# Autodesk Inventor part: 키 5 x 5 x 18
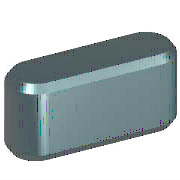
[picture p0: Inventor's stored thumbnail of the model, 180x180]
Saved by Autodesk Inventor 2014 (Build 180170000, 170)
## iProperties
IsCustomPart: 1
Created: 2012-02
Part Number: 키 5 x 5 x 18
Material: 강철, 연강
Description: 키 및 해당 키홈
Document SubType Name: Modeling
Standard: KS B 1311
Designer: mduedu
Standards Organization: KS
Language: ko-KR
Size Designation: 5 x 5 x 18
Categories: <MemberInstance><Categories><Category DisplayName="샤프트 부품" InternalName="7f7aeb1f-a693-4053-b835-cee3144e0d98" Mnemonic="SHFT"><Category DisplayName="키" Interna
Density: 7.86 g/cm^3
Appearance: 금색
Mass: 3.27476 g
Surface Area: 3.57848 cm^2
Volume: 0.416636 cm^3
Author: mduedu
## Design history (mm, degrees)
workplane "Work Plane1"
workplane "Work Plane2"
sketch "스케치1"
  geometry: L1 (2.5, 2.5)-(15.5, 2.5); L2 (15.5, -2.5)-(2.5, -2.5); L3 (0, 9.4)-(0, -7.4) reference; L4 (-5, 0)-(30, 0) reference; L5 (18, 0)-(18, 7); A1 r 2.5 centre (2.5, 0) between (2.5, 2.5) and (2.5, -2.5); A2 r 2.5 centre (15.5, 0) between (15.5, -2.5) and (15.5, 2.5)
  constraints: 6 end point, 5 point on circle, 4 tangent, 3 point on line, 2 centre point, 1 horizontal, 1 parallel, 1 perpendicular
  dimensions: "d0" = 2.5 radius of A1 (= 0.5 x PB); "d13" = 2.5 radius of A2 (= 0.5 x PB); "d14" = 18 distance between parallel lines of L5 L3 (= NLG)
extrude "본체1" new body sketch "스케치1" taper "d3" = 0 deg; stored distance "d4" = 10
workplane "Work Plane3"
body "Solid1"
chamfer "모따기1" distance "d8" = 0.4 (= PHH); stored, may be unused: second distance "d9" = 0.4 (= PHH), angle "d15" = 45 deg
other parameters: "d1" = -3 (= -PNT), "d2" = 2 (= PH - PNT), "NLG" = 18 [user parameter; used in 3 equation terms], "PB" = 5 [user parameter; used in 2 equation terms], "PNT" = 3 [user parameter; used in 2 equation terms], "PH" = 5 [user parameter; used in 1 equation term], "PHH" = 0.4 [user parameter; used in 2 equation terms], "d10" = 0, "d16" = 0, "d17" = 0, "d18" = 0, "WDMIN" = 12 [user parameter], "PLB2" = 18 (= NLG) [user parameter], "WDMAX" = 17 [user parameter], "PLB1" = 18 (= NLG) [user parameter], "RR" = 0.16 [user parameter], "PUEB" = 2.3 [user parameter]
